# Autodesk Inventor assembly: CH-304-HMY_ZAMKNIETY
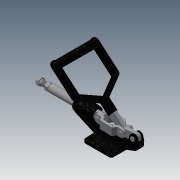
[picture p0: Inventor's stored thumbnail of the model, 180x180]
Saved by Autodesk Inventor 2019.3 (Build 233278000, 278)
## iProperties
Company: Î¢ÈíÖÐ¹ú
Created: 2015-08
Part Number: CH-304-HMY_ZAMKNIETY
Material: Ogólny
Description: STEP AP203
Document SubType Name: Assembly
Designer: CADENGINEERING4
Sending System: SolidWorks 2012
Preprocessor: SwSTEP 2.0
Title: CH-304-HMY.STEP
Author: Î¢ÈíÓÃ»§
Revision Number: ÈÎºÎ
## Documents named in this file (12)
- D:\Vault_2016\Projekty\STRONA\Push-pull clamp\CH-304-HMY\CH-304-HMY_ZAMKNIETY.iam
- D:\Vault_2016\Projekty\STRONA\Push-pull clamp\CH-304-HMY\CH-304-HM-01 BASE.ipt
- D:\Vault_2016\Projekty\STRONA\Push-pull clamp\CH-304-HMY\CH-304-HM-02 CREST STALK.ipt
- D:\Vault_2016\Projekty\STRONA\Push-pull clamp\CH-304-HMY\CH-304-HM-07.ipt
- D:\Vault_2016\Projekty\STRONA\Push-pull clamp\CH-304-HMY\CH-304-HM-04 CONNECTING-PLATE.ipt
- D:\Vault_2016\Projekty\STRONA\Push-pull clamp\CH-304-HMY\304-05.ipt
- D:\Vault_2016\Projekty\STRONA\Push-pull clamp\CH-304-HMY\5-16 LOCK NUT.ipt
- D:\Vault_2016\Projekty\STRONA\Push-pull clamp\CH-304-HMY\CH-304-HM-06.ipt
- D:\Vault_2016\Projekty\STRONA\Push-pull clamp\CH-304-HMY\M12 Nut.ipt
- D:\Vault_2016\Projekty\STRONA\Push-pull clamp\CH-304-HMY\CH-SA-125017 SPINDLE SUPPLIED.ipt
- D:\Vault_2016\Projekty\STRONA\Push-pull clamp\CH-304-HMY\CH-304-HMY-SHOUBA.ipt
- D:\Vault_2016\Projekty\STRONA\Push-pull clamp\CH-304-HMY\CH-304-HMY-06.ipt
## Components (15 placed, 15 different names)
1. CH-304-HM-01 BASE_1
2. CH-304-HM-02 CREST STALK_2
3. CH-304-HM-07_3
4. CH-304-HM-07_4
5. CH-304-HM-04 CONNECTING-PLATE_5
6. CH-304-HM-04 CONNECTING-PLATE_6
7. 304-05_7
8. 5-16 LOCK NUT_8
9. CH-304-HM-06_9
10. CH-304-HM-06_10
11. 5-16 LOCK NUT_11
12. M12 Nut_12
13. CH-SA-125017 SPINDLE SUPPLIED_13
14. CH-304-HMY-SHOUBA_14
15. CH-304-HMY-06_15
